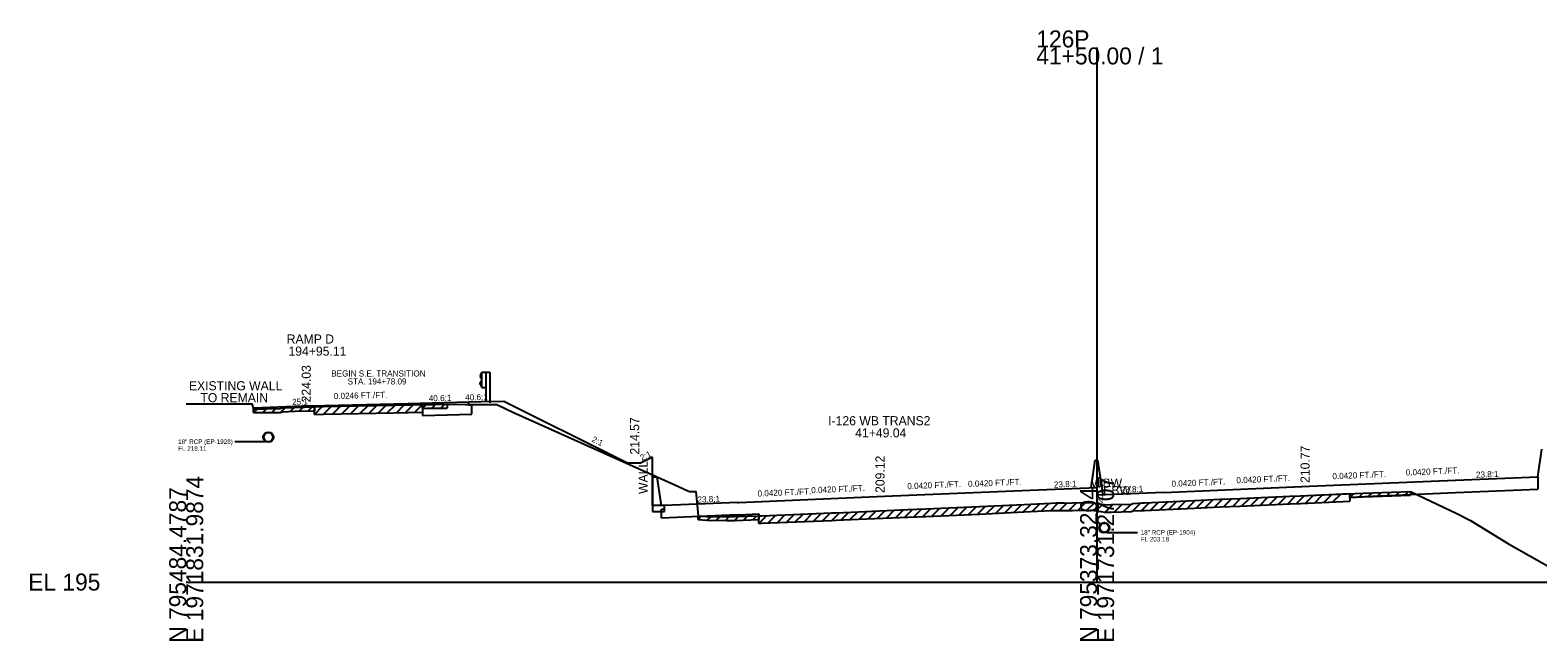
# Model space of a CAD drawing. Extents: x -161 to 1970889, y -4362 to 797231.
# Drawn here: x 974.3 to 1222.6, y 3990.3 to 4090.9 of the extents above; entities that cross this region are included whole.
import ezdxf

# ---------------------------------------------------------------- set-up
doc = ezdxf.new("R2010")
doc.units = 0
for name, color, linetype in [('RD_GPK_XS_Cell', 7, 'Continuous'), ('RD_XS_Base', 7, 'Continuous'), ('RD_XS_Box', 7, 'Continuous'), ('RD_XS_EarthShd', 7, 'Continuous'), ('RD_XS_ExGround', 7, 'Continuous'), ('RD_XS_ExPaveRet', 7, 'Continuous'), ('RD_XS_GR', 7, 'Continuous'), ('RD_XS_MedBWall', 7, 'Continuous'), ('RD_XS_Misc_Line', 7, 'Continuous'), ('RD_XS_Pave', 7, 'Continuous'), ('RD_XS_PaveOvlay', 7, 'Continuous'), ('RD_XS_PaveShd', 7, 'Continuous'), ('RD_XS_Pipe', 7, 'Continuous'), ('RD_XS_TieSlope', 7, 'Continuous'), ('RD_XS_TX_Elev_EX', 7, 'Continuous'), ('RD_XS_TX_Elev_PR', 7, 'Continuous'), ('RD_XS_TX_Misc', 7, 'Continuous'), ('RD_XS_TX_MkPT', 7, 'Continuous'), ('RD_XS_TX_Notes', 7, 'Continuous'), ('RD_XS_TX_Profile', 7, 'Continuous'), ('RD_XS_TX_ShdSlope', 7, 'Continuous'), ('RD_XS_TX_Slope', 7, 'Continuous'), ('RD_XS_TX_Station', 7, 'Continuous')]:
    doc.layers.add(name, color=color, linetype=linetype)

msp = doc.modelspace()

# ---------------------------------------------------------------- linework, layer by layer
at = {"layer": 'RD_GPK_XS_Cell'}
for p, q in [((1150, 4000), (1150, 4088.06)), ((1000, 4000), (1150, 4000)), ((1150, 4000), (1300, 4000))]:
    msp.add_line(p, q, dxfattribs=at)
at = {"layer": 'RD_XS_Base'}
for p, q in [((1046.55, 4029.11), (1046.55, 4029.67)), ((1038.94, 4027.44), (1047.05, 4027.64)), ((1047.05, 4029.12), (1046.55, 4029.11)), ((1047.05, 4027.64), (1047.05, 4029.12)), ((1191.62, 4014), (1209, 4014.73)), ((1209, 4014.73), (1222.58, 4015.3)), ((1078.79, 4012.04), (1078.79, 4012.6)), ((1078.29, 4012.02), (1078.79, 4012.04)), ((1078.29, 4010.54), (1078.29, 4012.02)), ((1090.8, 4011.07), (1078.29, 4010.54)), ((1090.8, 4011.07), (1091, 4011.07)), ((1091, 4011.07), (1094.3, 4011.21))]:
    msp.add_line(p, q, dxfattribs=at)
at = {"layer": 'RD_XS_Box'}
for p, q in [((1076.79, 4012.6), (1076.79, 4020.57)), ((1078.79, 4012.6), (1076.79, 4012.6))]:
    msp.add_line(p, q, dxfattribs=at)
at = {"layer": 'RD_XS_EarthShd'}
msp.add_line((1046.55, 4029.67), (1048.55, 4029.72), dxfattribs=at)
at = {"layer": 'RD_XS_ExGround'}
msp.add_lwpolyline([(1000, 4029.33), (1000.55, 4029.33), (1009.6, 4029.35), (1010.22, 4029.35), (1010.81, 4029.35), (1011.11, 4028.53), (1012.8, 4028.55), (1015.48, 4028.58), (1015.83, 4028.67), (1017.87, 4028.74), (1022.64, 4028.89), (1034.19, 4029.13), (1039.57, 4029.23), (1040.83, 4029.24), (1042.95, 4029.27), (1046.01, 4029.26), (1050.26, 4029.25), (1050.73, 4029.25), (1051.18, 4029.25), (1053.81, 4027.98), (1080.44, 4016), (1082.52, 4015.06), (1082.86, 4014.92), (1083.9, 4014.92), (1084.3, 4010.92), (1085.69, 4010.8), (1086.42, 4010.75), (1086.89, 4010.79), (1088.95, 4010.78), (1090.35, 4010.78), (1094.3, 4010.9), (1094.78, 4010.92), (1106.27, 4011.39), (1107.06, 4011.42), (1110.7, 4011.58), (1118.83, 4011.92), (1121.81, 4012.05), (1130.64, 4012.45), (1137.93, 4012.79), (1142.45, 4013.01), (1143.28, 4013.02), (1144.65, 4013.05), (1145.02, 4013.01), (1145.95, 4013.03), (1148.89, 4013.1), (1150, 4012.95), (1151.2, 4012.78), (1151.57, 4012.73), (1152.34, 4012.76), (1155.64, 4012.85), (1155.88, 4012.96), (1157.49, 4013.03), (1157.81, 4013.04), (1166.02, 4013.43), (1170.26, 4013.62), (1173.49, 4013.76), (1181.76, 4014.12), (1183.47, 4014.2), (1193.74, 4014.65), (1195.37, 4014.71), (1201.62, 4014.93), (1208.3, 4011.73), (1209.01, 4011.39), (1211.49, 4010.15), (1217.76, 4006.3), (1224.56, 4002.45)], dxfattribs=at)
at = {"layer": 'RD_XS_ExPaveRet'}
for p, q in [((1011.11, 4027.91), (1011.11, 4028.53)), ((1011.11, 4027.91), (1012.8, 4027.93)), ((1012.8, 4027.93), (1015.48, 4027.95)), ((1015.48, 4027.95), (1015.83, 4028.05)), ((1015.83, 4028.05), (1017.87, 4028.12)), ((1017.87, 4028.12), (1021.11, 4028.22)), ((1021.11, 4027.6), (1021.11, 4028.85)), ((1021.11, 4028.85), (1021.11, 4028.22)), ((1021.11, 4027.6), (1022.64, 4027.64)), ((1022.64, 4027.64), (1034.19, 4027.88)), ((1034.19, 4027.88), (1038.94, 4027.97)), ((1038.94, 4029.22), (1038.94, 4027.97)), ((1038.94, 4028.59), (1038.94, 4029.22)), ((1038.94, 4028.59), (1039.57, 4028.61)), ((1039.57, 4028.61), (1040.83, 4028.62)), ((1040.83, 4028.62), (1042.95, 4028.65)), ((1042.95, 4029.27), (1042.95, 4028.65)), ((1201.62, 4014.93), (1201.62, 4014.3)), ((1157.81, 4011.79), (1166.02, 4012.18)), ((1166.02, 4012.18), (1170.26, 4012.37)), ((1170.26, 4012.37), (1173.49, 4012.51)), ((1173.49, 4012.51), (1181.76, 4012.87)), ((1181.76, 4012.87), (1183.47, 4012.95)), ((1183.47, 4012.95), (1191.62, 4013.31)), ((1191.62, 4014.56), (1191.62, 4013.31)), ((1191.62, 4013.93), (1191.62, 4014.56)), ((1191.62, 4013.93), (1193.74, 4014.03)), ((1193.74, 4014.03), (1195.37, 4014.08)), ((1195.37, 4014.08), (1201.62, 4014.3)), ((1084.3, 4010.3), (1084.3, 4010.92)), ((1084.3, 4010.3), (1085.69, 4010.17)), ((1085.69, 4010.17), (1086.42, 4010.12)), ((1086.42, 4010.12), (1086.89, 4010.16)), ((1086.89, 4010.16), (1088.95, 4010.15)), ((1088.95, 4010.15), (1090.35, 4010.15)), ((1090.35, 4010.15), (1094.3, 4010.28)), ((1094.3, 4009.65), (1094.3, 4010.9)), ((1094.3, 4010.9), (1094.3, 4010.28)), ((1094.3, 4010.28), (1094.3, 4010.28)), ((1094.3, 4009.65), (1094.78, 4009.67)), ((1094.78, 4009.67), (1106.27, 4010.14)), ((1106.27, 4010.14), (1107.06, 4010.17)), ((1107.06, 4010.17), (1110.7, 4010.33)), ((1110.7, 4010.33), (1118.83, 4010.67)), ((1118.83, 4010.67), (1121.81, 4010.8)), ((1121.81, 4010.8), (1130.64, 4011.2)), ((1130.64, 4011.2), (1137.93, 4011.54)), ((1137.93, 4011.54), (1142.45, 4011.76)), ((1142.45, 4011.76), (1143.28, 4011.77)), ((1143.28, 4011.77), (1144.65, 4011.8)), ((1144.65, 4011.8), (1145.02, 4011.76)), ((1145.02, 4011.76), (1145.95, 4011.78)), ((1145.95, 4011.78), (1148.89, 4011.85)), ((1148.89, 4011.85), (1150, 4011.7)), ((1150, 4011.7), (1151.2, 4011.53)), ((1151.2, 4011.53), (1151.57, 4011.48)), ((1151.57, 4011.48), (1152.34, 4011.51)), ((1152.34, 4011.51), (1155.64, 4011.6)), ((1155.64, 4011.6), (1155.88, 4011.71)), ((1155.88, 4011.71), (1157.49, 4011.78)), ((1157.49, 4011.78), (1157.81, 4011.79))]:
    msp.add_line(p, q, dxfattribs=at)
at = {"layer": 'RD_XS_GR'}
for p, q in [((1048.69, 4034.43), (1048.42, 4033.99)), ((1048.69, 4034.59), (1049.36, 4034.59)), ((1048.69, 4032.02), (1048.69, 4034.59)), ((1049.36, 4034.59), (1050.03, 4034.59)), ((1049.36, 4034.59), (1049.36, 4029.65)), ((1050.03, 4034.59), (1050.03, 4029.54)), ((1048.42, 4033.99), (1048.42, 4033.88)), ((1048.42, 4033.88), (1048.69, 4033.44)), ((1048.42, 4032.73), (1048.69, 4033.17)), ((1048.42, 4032.62), (1048.42, 4032.73)), ((1048.69, 4032.18), (1048.42, 4032.62)), ((1048.69, 4032.02), (1049.36, 4032.02))]:
    msp.add_line(p, q, dxfattribs=at)
at = {"layer": 'RD_XS_MedBWall'}
for p, q in [((1149, 4015.55), (1149.67, 4020.09)), ((1149.67, 4020.09), (1150.14, 4020.09)), ((1151, 4014.34), (1150.14, 4020.09)), ((1222.58, 4017.34), (1223.25, 4021.89)), ((1077.54, 4017.27), (1076.79, 4017.27)), ((1076.79, 4017.27), (1076.79, 4011.6)), ((1078.29, 4012.6), (1077.54, 4017.27)), ((1222.58, 4017.34), (1222.58, 4015.3)), ((1078.79, 4012.6), (1078.29, 4012.6)), ((1078.79, 4011.6), (1078.79, 4012.6)), ((1076.79, 4011.6), (1078.79, 4011.6))]:
    msp.add_line(p, q, dxfattribs=at)
at = {"layer": 'RD_XS_Misc_Line'}
for p, q in [((1011.11, 4027.91), (1011.74, 4028.54)), ((1012.61, 4027.92), (1013.24, 4028.55)), ((1014.11, 4027.94), (1014.74, 4028.57)), ((1015.61, 4027.99), (1016.31, 4028.69)), ((1017.11, 4028.09), (1017.76, 4028.74)), ((1018.61, 4028.14), (1019.26, 4028.79)), ((1020.11, 4028.19), (1020.76, 4028.83)), ((1021.11, 4027.6), (1022.4, 4028.89)), ((1022.61, 4027.64), (1023.89, 4028.92)), ((1024.11, 4027.67), (1025.39, 4028.95)), ((1025.61, 4027.7), (1026.89, 4028.98)), ((1027.11, 4027.74), (1028.39, 4029.01)), ((1028.62, 4027.77), (1029.89, 4029.04)), ((1030.12, 4027.8), (1031.39, 4029.07)), ((1031.62, 4027.83), (1032.89, 4029.1)), ((1033.12, 4027.86), (1034.39, 4029.13)), ((1034.62, 4027.89), (1035.89, 4029.16)), ((1036.12, 4027.92), (1037.39, 4029.19)), ((1037.62, 4027.94), (1038.89, 4029.22)), ((1038.94, 4028.59), (1039.58, 4029.23)), ((1040.44, 4028.61), (1041.08, 4029.25)), ((1041.95, 4028.63), (1042.58, 4029.27)), ((1191.62, 4013.93), (1192.28, 4014.59)), ((1193.13, 4014), (1193.78, 4014.65)), ((1194.63, 4014.06), (1195.27, 4014.71)), ((1196.13, 4014.11), (1196.77, 4014.76)), ((1197.63, 4014.16), (1198.27, 4014.81)), ((1199.13, 4014.22), (1199.78, 4014.86)), ((1200.63, 4014.27), (1201.28, 4014.92)), ((1121.31, 4010.78), (1122.62, 4012.09)), ((1122.81, 4010.84), (1124.12, 4012.15)), ((1124.31, 4010.91), (1125.62, 4012.22)), ((1125.81, 4010.98), (1127.12, 4012.29)), ((1127.31, 4011.05), (1128.62, 4012.36)), ((1128.81, 4011.12), (1130.12, 4012.43)), ((1130.31, 4011.19), (1131.62, 4012.5)), ((1131.81, 4011.26), (1133.12, 4012.57)), ((1133.31, 4011.33), (1134.62, 4012.64)), ((1134.81, 4011.4), (1136.12, 4012.71)), ((1136.31, 4011.47), (1137.63, 4012.78)), ((1137.81, 4011.54), (1139.13, 4012.85)), ((1139.31, 4011.61), (1140.63, 4012.92)), ((1140.81, 4011.68), (1142.13, 4012.99)), ((1142.32, 4011.75), (1143.59, 4013.03)), ((1143.82, 4011.78), (1145.04, 4013.01)), ((1145.32, 4011.77), (1146.6, 4013.05)), ((1146.82, 4011.8), (1148.1, 4013.08)), ((1148.32, 4011.83), (1149.5, 4013.01)), ((1149.82, 4011.72), (1150.92, 4012.82)), ((1151.32, 4011.52), (1152.57, 4012.76)), ((1152.82, 4011.52), (1154.11, 4012.81)), ((1154.32, 4011.56), (1155.61, 4012.85)), ((1155.82, 4011.68), (1157.15, 4013.01)), ((1157.32, 4011.77), (1158.63, 4013.08)), ((1158.82, 4011.84), (1160.13, 4013.15)), ((1160.32, 4011.91), (1161.63, 4013.22)), ((1161.82, 4011.98), (1163.13, 4013.29)), ((1163.32, 4012.05), (1164.63, 4013.36)), ((1164.82, 4012.12), (1166.13, 4013.43)), ((1166.32, 4012.19), (1167.63, 4013.5)), ((1167.82, 4012.26), (1169.14, 4013.57)), ((1169.32, 4012.33), (1170.63, 4013.64)), ((1170.83, 4012.4), (1172.13, 4013.7)), ((1172.33, 4012.46), (1173.63, 4013.77)), ((1173.83, 4012.53), (1175.13, 4013.83)), ((1175.33, 4012.59), (1176.63, 4013.9)), ((1176.83, 4012.66), (1178.13, 4013.96)), ((1178.33, 4012.72), (1179.63, 4014.03)), ((1179.83, 4012.79), (1181.14, 4014.09)), ((1181.33, 4012.85), (1182.64, 4014.16)), ((1182.83, 4012.92), (1184.14, 4014.23)), ((1184.33, 4012.98), (1185.64, 4014.29)), ((1185.83, 4013.05), (1187.14, 4014.36)), ((1187.33, 4013.12), (1188.64, 4014.43)), ((1188.83, 4013.18), (1190.14, 4014.49)), ((1084.3, 4010.3), (1084.87, 4010.87)), ((1085.8, 4010.16), (1086.38, 4010.75)), ((1087.3, 4010.16), (1087.92, 4010.78)), ((1088.8, 4010.15), (1089.42, 4010.78)), ((1090.3, 4010.15), (1090.94, 4010.8)), ((1091.8, 4010.2), (1092.45, 4010.85)), ((1093.3, 4010.25), (1093.95, 4010.89)), ((1094.3, 4009.65), (1095.6, 4010.95)), ((1095.8, 4009.71), (1097.1, 4011.01)), ((1097.3, 4009.77), (1098.6, 4011.08)), ((1098.8, 4009.83), (1100.1, 4011.14)), ((1100.3, 4009.9), (1101.6, 4011.2)), ((1101.8, 4009.96), (1103.1, 4011.26)), ((1103.3, 4010.02), (1104.61, 4011.32)), ((1104.8, 4010.08), (1106.11, 4011.38)), ((1106.3, 4010.14), (1107.61, 4011.45)), ((1107.8, 4010.2), (1109.11, 4011.51)), ((1109.3, 4010.27), (1110.61, 4011.57)), ((1110.8, 4010.33), (1112.11, 4011.64)), ((1112.3, 4010.39), (1113.61, 4011.7)), ((1113.81, 4010.46), (1115.11, 4011.76)), ((1115.31, 4010.52), (1116.61, 4011.83)), ((1116.81, 4010.59), (1118.11, 4011.89)), ((1118.31, 4010.65), (1119.61, 4011.96)), ((1119.81, 4010.71), (1121.11, 4012.02))]:
    msp.add_line(p, q, dxfattribs=at)
at = {"layer": 'RD_XS_Pave'}
for p, q in [((1020.52, 4029.03), (1036.54, 4029.42)), ((1115, 4014.12), (1139, 4015.13)), ((1161, 4014.76), (1185, 4015.77)), ((1185, 4015.77), (1209, 4016.77)), ((1090.8, 4013.11), (1091, 4013.11)), ((1091, 4013.11), (1115, 4014.12))]:
    msp.add_line(p, q, dxfattribs=at)
at = {"layer": 'RD_XS_PaveOvlay'}
for p, q in [((1021.11, 4028.85), (1022.64, 4028.89)), ((1022.64, 4028.89), (1034.19, 4029.13)), ((1034.19, 4029.13), (1038.94, 4029.22)), ((1038.94, 4029.22), (1038.94, 4027.44)), ((1121.81, 4012.05), (1130.64, 4012.45)), ((1130.64, 4012.45), (1137.93, 4012.79)), ((1137.93, 4012.79), (1142.45, 4013.01)), ((1142.45, 4013.01), (1143.28, 4013.02)), ((1143.28, 4013.02), (1144.65, 4013.05)), ((1144.65, 4013.05), (1145.02, 4013.01)), ((1145.02, 4013.01), (1145.95, 4013.03)), ((1145.95, 4013.03), (1148.89, 4013.1)), ((1148.89, 4013.1), (1150, 4012.95)), ((1150, 4012.95), (1151.2, 4012.78)), ((1151.2, 4012.78), (1151.57, 4012.73)), ((1151.57, 4012.73), (1152.34, 4012.76)), ((1152.34, 4012.76), (1155.64, 4012.85)), ((1155.64, 4012.85), (1155.88, 4012.96)), ((1155.88, 4012.96), (1157.49, 4013.03)), ((1157.49, 4013.03), (1157.81, 4013.04)), ((1157.81, 4013.04), (1166.02, 4013.43)), ((1166.02, 4013.43), (1170.26, 4013.62)), ((1170.26, 4013.62), (1173.49, 4013.76)), ((1173.49, 4013.76), (1181.76, 4014.12)), ((1181.76, 4014.12), (1183.47, 4014.2)), ((1183.47, 4014.2), (1191.62, 4014.56)), ((1191.62, 4014.56), (1191.62, 4014)), ((1094.3, 4011.21), (1094.3, 4010.9)), ((1094.3, 4010.9), (1094.78, 4010.92)), ((1094.78, 4010.92), (1106.27, 4011.39)), ((1106.27, 4011.39), (1107.06, 4011.42)), ((1107.06, 4011.42), (1110.7, 4011.58)), ((1110.7, 4011.58), (1118.83, 4011.92)), ((1118.83, 4011.92), (1121.81, 4012.05))]:
    msp.add_line(p, q, dxfattribs=at)
msp.add_lwpolyline([(1011.07, 4028.65), (1011.11, 4028.53), (1012.8, 4028.55), (1015.48, 4028.58), (1015.83, 4028.67), (1017.87, 4028.74), (1021.11, 4028.85)], dxfattribs=at)
at = {"layer": 'RD_XS_PaveShd'}
for p, q in [((1036.54, 4029.42), (1046.55, 4029.67)), ((1020.52, 4029.03), (1011.07, 4028.65)), ((1209, 4016.77), (1222.58, 4017.34)), ((1139, 4015.13), (1150, 4015.59)), ((1150, 4014.3), (1150, 4015.59)), ((1161, 4014.76), (1150, 4014.3)), ((1090.8, 4013.11), (1078.79, 4012.6))]:
    msp.add_line(p, q, dxfattribs=at)
at = {"layer": 'RD_XS_Pipe'}
for p, q in [((1013.03, 4023.11), (1008.03, 4023.11)), ((1151.68, 4008.18), (1156.68, 4008.18))]:
    msp.add_line(p, q, dxfattribs=at)
for centre, radius in [((1013.53, 4023.86), 0.85), ((1013.53, 4023.86), 0.75), ((1151.18, 4008.93), 0.85), ((1151.18, 4008.93), 0.75)]:
    msp.add_circle(centre, radius, dxfattribs=at)
at = {"layer": 'RD_XS_TieSlope'}
for p, q in [((1048.55, 4029.72), (1052.3, 4029.81)), ((1052.3, 4029.81), (1070.79, 4020.57)), ((1070.79, 4020.57), (1072.79, 4019.57)), ((1074.79, 4019.57), (1072.79, 4019.57)), ((1076.79, 4020.57), (1074.79, 4019.57))]:
    msp.add_line(p, q, dxfattribs=at)

# ---------------------------------------------------------------- texts
at = {"layer": 'RD_GPK_XS_Cell'}
for s, p in [('126P', (1140, 4088.06)), ('41+50.00 / 1', (1140, 4085.26)), ('EL 195', (974, 3998.6))]:
    msp.add_text(s, height=2.8, dxfattribs=at).set_placement(p)
for s, p in [('E 1971831.9874', (1002.8, 3990)), ('E 1971731.2707', (1152.8, 3990)), ('N 795484.4787', (1000, 3990)), ('N 795373.3204', (1150, 3990))]:
    msp.add_text(s, height=2.8, rotation=90, dxfattribs=at).set_placement(p)
at = {"layer": 'RD_XS_Pipe'}
for s, p in [('18" RCP (EP-1928)', (998.68, 4022.74)), ('FL 218.11', (998.68, 4021.61)), ('18" RCP (EP-1904)', (1157.18, 4007.8)), ('FL 203.18', (1157.18, 4006.68))]:
    msp.add_text(s, height=0.75, dxfattribs=at).set_placement(p)
at = {"layer": 'RD_XS_TX_Elev_EX'}
msp.add_text('207.95', height=1, rotation=90, dxfattribs=at).set_placement((1151, 4012.95))
at = {"layer": 'RD_XS_TX_Elev_PR'}
for s, p in [(' 224.03', (1020.52, 4029.03)), (' 210.77', (1185, 4015.77)), (' 209.12', (1115, 4014.12))]:
    msp.add_text(s, height=1.5, rotation=90, dxfattribs=at).set_placement(p)
at = {"layer": 'RD_XS_TX_Misc'}
msp.add_text('214.57', height=1.5, rotation=90, dxfattribs=at).set_placement((1074.6, 4020.99))
at = {"layer": 'RD_XS_TX_MkPT'}
for s, p in [('WBW', (1149, 4015.55)), ('EBW', (1151, 4014.34))]:
    msp.add_text(s, height=1.5, dxfattribs=at).set_placement(p)
at = {"layer": 'RD_XS_TX_Notes'}
for s, height, p in [('BEGIN S.E. TRANSITION', 1, (1023.89, 4033.85)), ('EXISTING WALL', 1.5, (1000.45, 4031.58)), ('STA. 194+78.09', 1, (1026.58, 4032.54)), ('TO REMAIN', 1.5, (1002.34, 4029.61))]:
    msp.add_text(s, height=height, dxfattribs=at).set_placement(p)
msp.add_text('WALL', height=1.5, rotation=90, dxfattribs=at).set_placement((1076.01, 4014.5))
at = {"layer": 'RD_XS_TX_Profile'}
for s, rotation, p in [('40.6:1', 1.4115, (1039.96, 4029.75)), ('23.8:1', 2.405, (1212.41, 4017.17)), ('23.8:1', 2.405, (1142.91, 4015.54)), ('23.8:1', 2.405, (1153.91, 4014.71)), ('23.8:1', 2.4033, (1084.21, 4013.08))]:
    msp.add_text(s, height=1, rotation=rotation, dxfattribs=at).set_placement(p)
at = {"layer": 'RD_XS_TX_ShdSlope'}
msp.add_text('40.6:1', height=1, rotation=1.4115, dxfattribs=at).set_placement((1045.96, 4029.9))
at = {"layer": 'RD_XS_TX_Slope'}
for s, rotation, p in [('25:1', 2.2886, (1017.46, 4029.15)), ('0.0246 FT./FT.', 1.4115, (1024.31, 4030.13)), ('2:1', 333.4552, (1066.7, 4023.17)), ('2:1', 26.5651, (1075.03, 4019.94)), ('0.0420 FT./FT.', 2.405, (1172.96, 4016.26)), ('0.0420 FT./FT.', 2.405, (1188.77, 4016.92)), ('0.0420 FT./FT.', 2.405, (1200.85, 4017.53)), ('0.0420 FT./FT.', 2.405, (1094.11, 4014.07)), ('0.0420 FT./FT.', 2.4033, (1102.95, 4014.62)), ('0.0420 FT./FT.', 2.405, (1118.77, 4015.28)), ('0.0420 FT./FT.', 2.405, (1128.77, 4015.65)), ('0.0420 FT./FT.', 2.405, (1162.28, 4015.68))]:
    msp.add_text(s, height=1, rotation=rotation, dxfattribs=at).set_placement(p)
at = {"layer": 'RD_XS_TX_Station'}
for s, p in [('RAMP D', (1016.55, 4039.28)), ('194+95.11', (1016.84, 4037.28)), ('I-126 WB TRANS2', (1105.72, 4025.82)), ('41+49.04', (1110.17, 4023.82))]:
    msp.add_text(s, height=1.5, dxfattribs=at).set_placement(p)

doc.saveas('drawing.dxf')
